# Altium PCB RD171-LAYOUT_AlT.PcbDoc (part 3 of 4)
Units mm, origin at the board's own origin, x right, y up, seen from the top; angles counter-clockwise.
Board outline 318.5 x 127 mm, 6 copper layers (TOP, Mid-Layer 1, Mid-Layer 2, Mid-Layer 3, Mid-Layer 4, BOTTOM), stack 1.422 mm thick; 473 components, 225 nets, 1188 pads, 1192 vias.
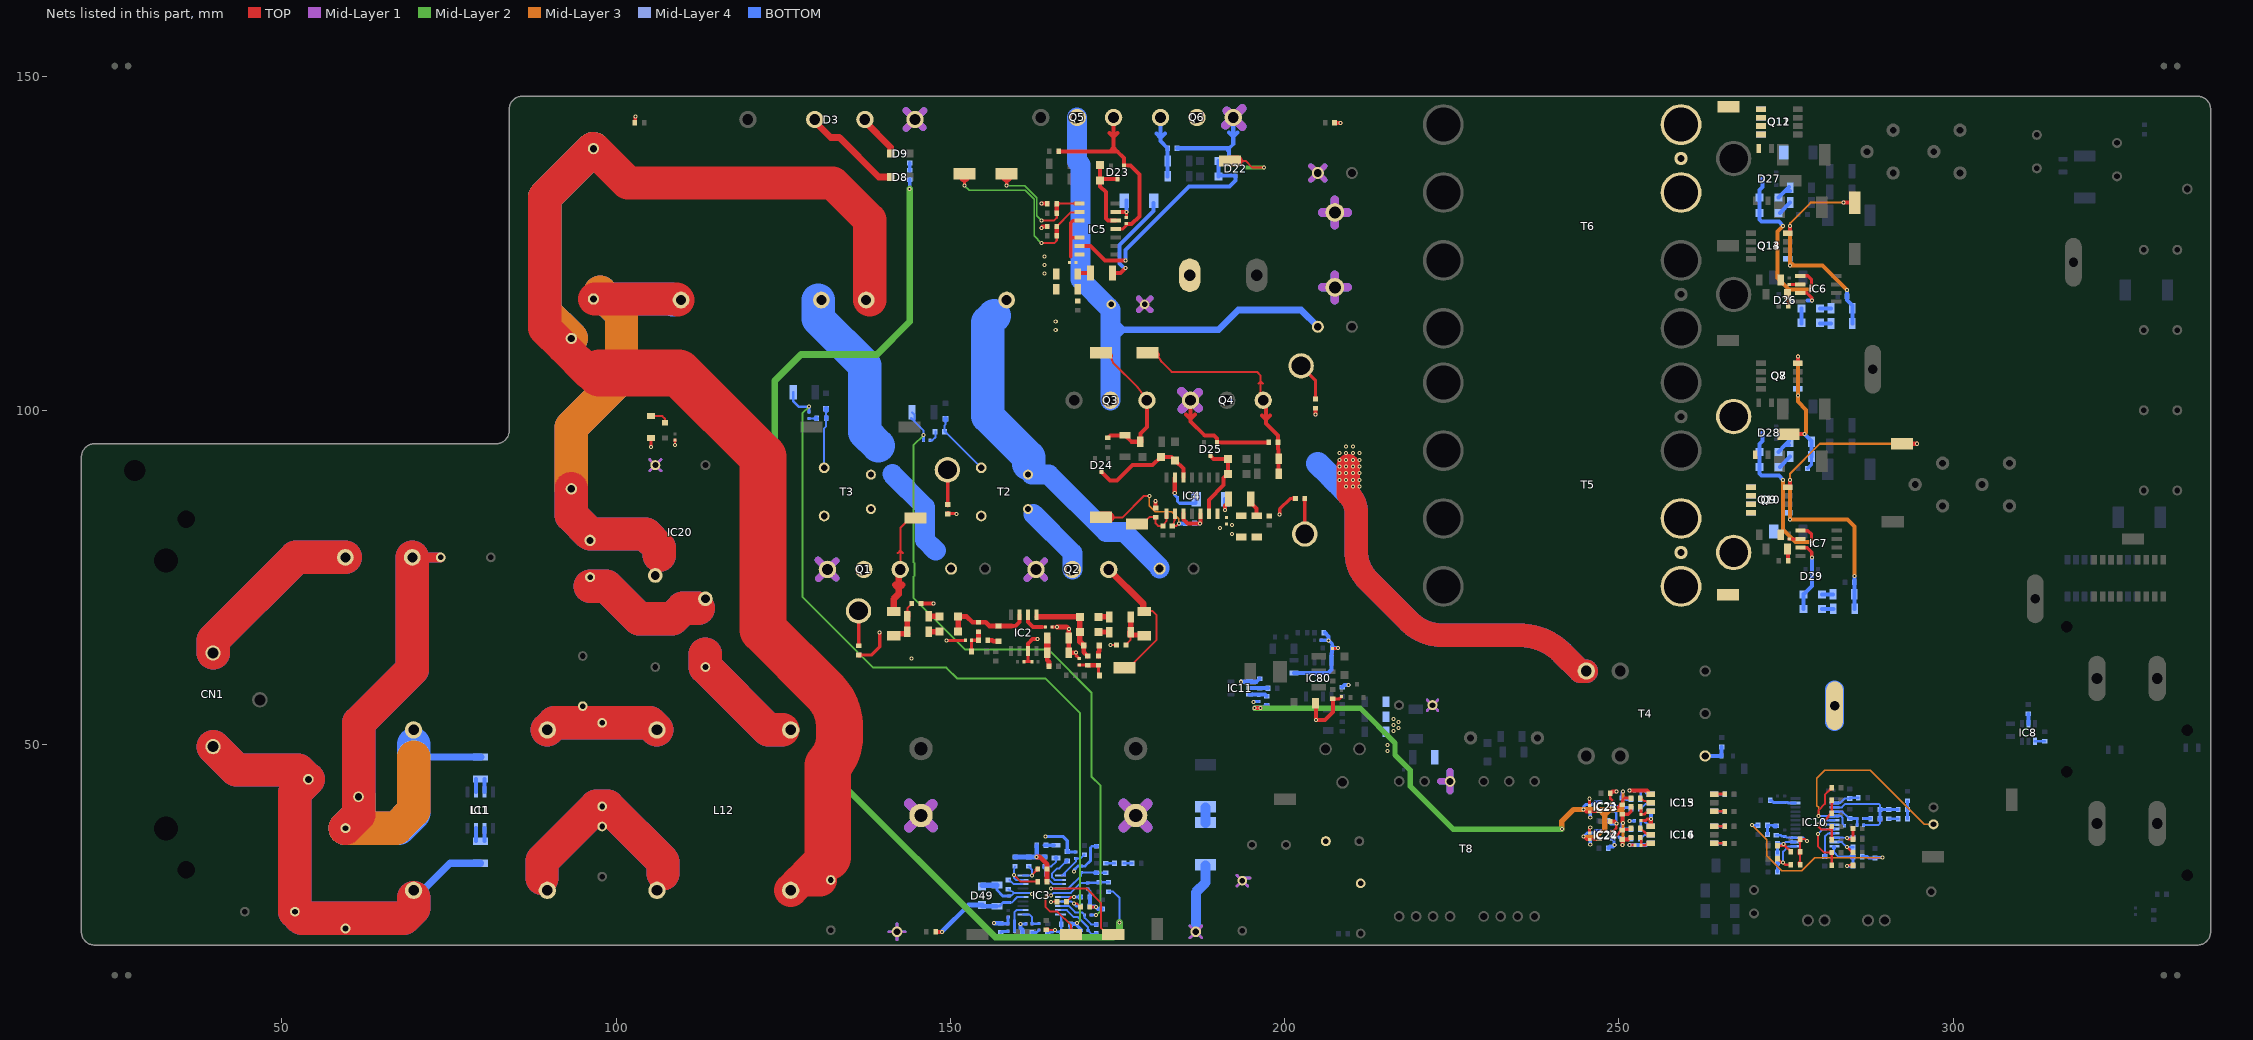
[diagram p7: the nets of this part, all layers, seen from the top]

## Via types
v1: diameter 0.6, hole 0.3, TOP to BOTTOM, 1184 vias
v2: diameter 7, hole 3.2, TOP to BOTTOM, 8 vias

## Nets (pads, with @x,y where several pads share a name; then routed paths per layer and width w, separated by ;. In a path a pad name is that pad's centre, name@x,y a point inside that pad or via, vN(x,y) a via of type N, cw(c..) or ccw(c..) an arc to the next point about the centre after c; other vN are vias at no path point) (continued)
PN: C1.1 C7.1 C34.1 C35.1 C36.1 C37.1 C38.1 C39.1 C40.1 C42.1 C43.1 C45.1 C47.1 C48.1 C49.1 C50.1 C53.1 C54.1 C55.1 C56.1 C57.1 C58.1 C62.1 C66.1 C67.1 C70.1 C71.1 C72.1 C73.1 C74.1 C75.1 C76.1 C77.1 C80.1 C81.1 C82.1 C83.1 C84.1 C85.1 C86.1 C87.1 C95.1 C96.1 C97.1 C98.1 C101.1 C103.1 C800.1 C802.1 C803.1 C804.1 C805.2 C806.2 C808.2 C811.2 C812.1 D3.4 D18.A D22.A D25.A D49.A D50.C HS5.1 HS6.1 IC2.3 IC3.16 IC4.3 IC4.5 IC5.3 IC5.5 IC11.1 IC13.4 IC14.4 IC15.4 IC16.4 IC20.2 IC21.3 IC22.3 IC23.3 IC24.3 IC80.GND Q1.S Q2.S Q4.S Q6.S R2.1 R7.1 R8.1 R29.1 R33.1 R71.1 R73.1 R90.1 R93.1 R96.1 R98.1 R99.1 R100.1 R101.1 R102.1 R103.1 R104.1 R174.1 R175.1 R176.1 R179.1 R187.1 R189.1 R191.1 R193.1 R198.1 R220.1 R221.1 R222.1 R223.1 R224.1 R225.1 R801.2 R807.1 R809.1 R811.2 R812.1 R813.1 R814.1 T2.2 T3.2 T8.4 TP43.1 TP45.1 | length 638.4
  TOP w0.3: v1(108.8,94.8) C70.1@108.8,95.396 ; v1(165.05,26.45) 165.459,26.5 R175.1@165.95,26.5 R175.1@166.01,26.5 ; v1(173.95,64.9) R71.1@174.85,64.9 R71.1@174.91,64.9
  TOP w0.4: v1(105.2,94.5) D50.C@105.2,95.695 ; C70.1@108.8,95.396 C70.1@108.8,95.525 C70.1@108.8,95.55 ; R191.1@248.7,42.7 248.7,41.95 248.95,41.7 IC23.3@248.95,41.25 ; IC24.3@248.95,37.05 249.15,37.05 249.6,37.5 v1(249.6,38.2)
  TOP w0.45: v1(149.4,65.6) C37.1@152.2,65.6 ; C81.1@161,62.4 161.585,62.4 ; IC2.3@161.585,63.95 161.585,62.4 ; C80.1@162.15,62.4 161.585,62.4 ; v1(168.75,63.75) 168.75,63.375 C35.1@169.25,62.875 ; C808.2@207.15,64.4 207.95,64.4 v1(208,64.45) ; R811.2@207.2,56.85 208.175,56.85 C805.2@208.5,57.175 ; C98.1@245.6,36.775 245.6,37.5 v1(245.7,37.6) ; C97.1@245.6,40.875 v1(245.6,41.9) ; v1(251.6,34.95) C74.1@252.35,34.95 ; C73.1@253.275,38.625 253.95,38.625 254.175,38.85 254.75,38.85 v1@254.8,38.85
  TOP w0.5: R225.1@102.86,143 v1(102.86,143.92) v1@102.87,143.93 ; R222.1@136.583,63.4 138.14,63.4 139.4,64.66 v1(139.4,66.8) ; R220.1@149.68,84.56 150.84,84.56 v1(150.9,84.5) ; C62.1@165.2,67.6 v1(165.95,67.6) ; 168,122.95 168,125.83 ; IC5.5@169.3,125.83 168,125.83 ; IC5.3@169.447,128.37 IC5.3@169.3,128.37 168.3,128.37 168,128.07 168,125.83 ; R176.1@170.85,25.7 v1(171.75,25.7) ; v1(199.25,84.4) 199.25,85.25 200.8,86.8 R221.1@201.325,86.8
  TOP w0.6: R73.1@145.65,71.1 v1(147.5,71.1) ; IC2.3@161.585,64 161.585,65.085 162.3,65.8 v1(163,65.8) ; v1(163.6,127.3) 163.8,127.5 C53.1@164.5,127.5 ; v1(163.6,130.9) C54.1@164.5,130.9 ; C57.1@180.7,85.4 v1(180.7,86.4) ; IC4.3@184.83,84.55 184.83,83.7 185.43,83.1 v1(187.35,83.1) 187.37,83.12 IC4.5@187.37,84.5 ; 185.25,99.35 185.9,98.7 ; Q4.S@185.9,101.5 185.9,98.7 ; 186.55,99.35 185.9,98.7 ; R33.1@197.6,95.2 D25.A@189.85,95.2 189.85,95.8 189.45,96.2 188.038,96.2 185.9,98.337 185.9,98.7 ; v1(204.6,99.35) R223.1@204.6,100.25 ; C806.2@204.65,56.2 v1(204.65,53.65) 206,53.65 207.2,54.85 R811.2@207.2,56.85 ; R224.1@207.45,143 v1(208.35,143) ; R193.1@248.7,38.5 249.3,38.5 v1(249.6,38.2) ; R191.1@248.7,42.7 249,43 v1(249.6,43) ; v1(251.55,43.1) 254.22,43.1 IC15.4@254.75,42.57 ; IC16.4@254.75,37.75 IC16.4@254.75,37.77 254.75,38.85 v1(254.8,38.9)
  TOP w0.7: D50.C@105.2,95.695 D50.C@105.2,95.863 ; R222.1@136.3,63.4 R222.1@136.583,63.4 ; v1(162.9,33.2) 163.35,33.2 164.45,32.1 R198.1@164.45,29.5 ; v1(165.95,67.6) 167.4,67.6 v1(167.7,67.3) C82.1@167.7,65.95 C83.1@167.7,63.75 ; C83.1@167.75,63.75 v1(168.75,63.75) ; R221.1@201.325,86.8 R221.1@201.6,86.8
  TOP w0.72: R220.1@149.6,84.56 R220.1@149.68,84.56
  Mid-Layer 1 w0.4: 105,90.95 IC20.2@105.85,91.8 ; 105,92.65 IC20.2@105.85,91.8 ; 106.7,90.95 IC20.2@105.85,91.8 ; 106.7,92.65 IC20.2@105.85,91.8 ; 140.8,22 TP43.1@142,22 ; 142,20.8 TP43.1@142,22 ; 142,23.2 TP43.1@142,22 ; 143.2,22 TP43.1@142,22 ; 185.8,21.1 TP45.1@186.7,22 ; 185.8,22.9 TP45.1@186.7,22 ; 187.6,21.1 TP45.1@186.7,22 ; 187.6,22.9 TP45.1@186.7,22 ; 192.85,28.85 C101.1@193.65,29.65 ; 192.85,30.45 C101.1@193.65,29.65 ; 194.45,28.85 C101.1@193.65,29.65 ; 194.85,30.05 194.05,30.05 C101.1@193.65,29.65 ; 221.3,55.1 C804.1@222.1,55.9 ; 221.3,56.7 C804.1@222.1,55.9 ; 222.9,55.1 C804.1@222.1,55.9 ; 222.9,56.7 C804.1@222.1,55.9
  Mid-Layer 1 w0.8: 178.15,114.95 C103.1@179.05,115.85 ; 178.15,116.75 C103.1@179.05,115.85 ; 179.95,114.95 C103.1@179.05,115.85 ; 179.95,116.75 C103.1@179.05,115.85 ; 203.9,134.45 D18.A@204.95,135.5 ; 203.9,136.55 D18.A@204.95,135.5 ; 206,134.45 D18.A@204.95,135.5 ; 206,136.55 D18.A@204.95,135.5
  Mid-Layer 1 w1: 130.2,77.6 Q1.S@131.6,76.2 ; 130.25,74.85 Q1.S@131.6,76.2 ; 132.9,74.9 Q1.S@131.6,76.2 ; 132.9,77.5 Q1.S@131.6,76.2 ; 143.35,144.85 D3.4@144.7,143.5 ; 143.4,142.2 D3.4@144.7,143.5 ; 145.95,142.25 D3.4@144.7,143.5 ; 146,144.8 D3.4@144.7,143.5 ; 161.4,77.6 Q2.S@162.8,76.2 ; 161.45,74.85 Q2.S@162.8,76.2 ; 164.1,74.9 Q2.S@162.8,76.2 ; 164.1,77.5 Q2.S@162.8,76.2 ; 223.3,44.5 T8.4@224.73,44.5 ; 224.73,43.1 T8.4@224.73,44.5 ; 224.73,46 T8.4@224.73,44.5
  Mid-Layer 1 w1.3: 184.55,102.85 Q4.S@185.9,101.5 ; 184.58,100.18 Q4.S@185.9,101.5 ; 187.09,100.31 Q4.S@185.9,101.5 ; 187.09,102.69 Q4.S@185.9,101.5 ; 191.14,142.64 Q6.S@192.3,143.8 ; 191.31,144.79 Q6.S@192.3,143.8 ; 193.65,142.45 Q6.S@192.3,143.8 ; 193.65,145.15 Q6.S@192.3,143.8 ; 205.6,118.4 HS5.1@207.5,118.4 ; 205.6,129.6 HS6.1@207.5,129.6 ; 207.5,116.5 HS5.1@207.5,118.4 ; 207.5,120.3 HS5.1@207.5,118.4 ; 207.5,127.7 HS6.1@207.5,129.6 ; 207.5,131.5 HS6.1@207.5,129.6 ; 209.4,118.4 HS5.1@207.5,118.4 ; 209.4,129.6 HS6.1@207.5,129.6
  Mid-Layer 1 w1.5: 143.8,37.6 C7.1@145.6,39.4 ; 143.8,41.2 C7.1@145.6,39.4 ; 147.35,37.65 C7.1@145.6,39.4 ; 147.35,41.15 C7.1@145.6,39.4 ; 175.9,37.6 C1.1@177.7,39.4 ; 175.9,41.2 C1.1@177.7,39.4 ; 179.5,37.6 C1.1@177.7,39.4 ; 179.5,41.2 C1.1@177.7,39.4
  Mid-Layer 2 w0.3: v1(128.85,100.55) 127.85,99.55 127.85,72.084 138.434,61.5 149.4,61.5 151.05,59.85 164.25,59.85 169.4,54.7 169.4,23.75 v1(168.95,23.3) ; v1(146,96.3) 144.45,94.75 144.45,77.3 144.63,77.12 144.63,75.28 144.45,75.1 144.45,71.951 152.151,64.25 164.6,64.25 171.1,57.75 171.1,45.2 172.45,43.85 172.45,25.15 v1(171.8,24.5)
  Mid-Layer 4 w0.4: 105,90.95 IC20.2@105.85,91.8 ; 105,92.65 IC20.2@105.85,91.8 ; 106.7,90.95 IC20.2@105.85,91.8 ; 106.7,92.65 IC20.2@105.85,91.8 ; 140.8,22 TP43.1@142,22 ; 142,20.8 TP43.1@142,22 ; 142,23.2 TP43.1@142,22 ; 143.2,22 TP43.1@142,22 ; 185.8,21.1 TP45.1@186.7,22 ; 185.8,22.9 TP45.1@186.7,22 ; 187.6,21.1 TP45.1@186.7,22 ; 187.6,22.9 TP45.1@186.7,22 ; 192.85,28.85 C101.1@193.65,29.65 ; 192.85,30.45 C101.1@193.65,29.65 ; 194.45,28.85 C101.1@193.65,29.65 ; 194.7,30.05 194.05,30.05 C101.1@193.65,29.65 ; 221.3,55.1 C804.1@222.1,55.9 ; 221.3,56.7 C804.1@222.1,55.9 ; 222.9,55.1 C804.1@222.1,55.9 ; 222.9,56.7 C804.1@222.1,55.9
  Mid-Layer 4 w0.8: 178.15,114.95 C103.1@179.05,115.85 ; 178.15,116.75 C103.1@179.05,115.85 ; 179.95,114.95 C103.1@179.05,115.85 ; 179.95,116.75 C103.1@179.05,115.85 ; 203.9,134.45 D18.A@204.95,135.5 ; 203.9,136.55 D18.A@204.95,135.5 ; 206,134.45 D18.A@204.95,135.5 ; 206,136.55 D18.A@204.95,135.5
  Mid-Layer 4 w1: 130.2,77.6 Q1.S@131.6,76.2 ; 130.25,74.85 Q1.S@131.6,76.2 ; 132.9,74.9 Q1.S@131.6,76.2 ; 132.9,77.5 Q1.S@131.6,76.2 ; 143.35,142.15 D3.4@144.7,143.5 ; 143.35,144.85 D3.4@144.7,143.5 ; 145.95,142.25 D3.4@144.7,143.5 ; 146.05,144.85 D3.4@144.7,143.5 ; 161.4,77.6 Q2.S@162.8,76.2 ; 161.45,74.85 Q2.S@162.8,76.2 ; 164.1,74.9 Q2.S@162.8,76.2 ; 164.1,77.5 Q2.S@162.8,76.2 ; 223.3,44.5 T8.4@224.73,44.5 ; 224.73,43 T8.4@224.73,44.5 ; 224.73,46 T8.4@224.73,44.5
  Mid-Layer 4 w1.3: 184.55,102.85 Q4.S@185.9,101.5 ; 184.58,100.18 Q4.S@185.9,101.5 ; 187.09,100.31 Q4.S@185.9,101.5 ; 187.09,102.69 Q4.S@185.9,101.5 ; 191.14,142.64 Q6.S@192.3,143.8 ; 191.31,144.79 Q6.S@192.3,143.8 ; 193.65,142.45 Q6.S@192.3,143.8 ; 193.65,145.15 Q6.S@192.3,143.8 ; 205.6,118.4 HS5.1@207.5,118.4 ; 205.6,129.6 HS6.1@207.5,129.6 ; 207.5,116.5 HS5.1@207.5,118.4 ; 207.5,120.3 HS5.1@207.5,118.4 ; 207.5,127.7 HS6.1@207.5,129.6 ; 207.5,131.5 HS6.1@207.5,129.6 ; 209.4,118.4 HS5.1@207.5,118.4 ; 209.4,129.6 HS6.1@207.5,129.6
  Mid-Layer 4 w1.5: 143.8,37.6 C7.1@145.6,39.4 ; 143.8,41.2 C7.1@145.6,39.4 ; 147.35,41.15 C7.1@145.6,39.4 ; 147.4,37.6 C7.1@145.6,39.4 ; 175.9,37.6 C1.1@177.7,39.4 ; 175.9,41.2 C1.1@177.7,39.4 ; 179.5,37.6 C1.1@177.7,39.4 ; 179.5,41.2 C1.1@177.7,39.4
  BOTTOM w0.3: R8.1@144.1,98.85 144.65,98.3 ; R8.1@144.25,99.7 144.65,99.3 144.65,98.3 ; v1(146,96.3) 146,96.95 144.65,98.3 ; C49.1@158.65,28.35 159.55,27.825 ; C47.1@158.8,27.325 158.85,27.4 159.125,27.4 159.55,27.825 ; v1(162.2,27.65) 161.85,27.825 IC3.16@160.85,27.825 159.55,27.825
  BOTTOM w0.4: R7.1@126.5,102.7 126.5,101.35 127.3,100.55 v1(128.85,100.55) C36.1@128.85,99.725 C36.1@128.85,99.7 ; C39.1@169.55,31.825 170.15,31.825 170.95,32.625 170.95,34.55 171.2,34.8 R90.1@171.725,34.8 ; IC22.3@249.05,35.85 249.25,35.85 249.25,35 v1(249.3,34.95) ; IC21.3@249.05,40.15 249.3,40.15 IC21.3@249.45,40 ; IC21.3@249.35,40.1 249.6,39.85 v1(249.6,38.2)
  BOTTOM w0.45: C34.1@145.975,95.5 145.975,96.275 v1(146,96.3) ; C48.1@156.95,29 156.95,28.95 156.95,28.25 157.875,27.325 C47.1@158.825,27.325 ; C43.1@158.625,23.2 C42.1@158.625,24.2 ; v1(160.5,23.2) C45.1@161.275,23.2 ; R104.1@167.692,33.925 C50.1@168.725,33.925 ; v1(168.45,31.05) 168.45,31.2 169.075,31.825 C39.1@169.55,31.825 ; v1@168.7,23.15 168.95,22.9 ; v1(168.95,23.3) 168.95,22.9 ; C76.1@169.625,22.225 168.95,22.9 ; C38.1@170.55,28.375 170.85,28.075 R102.1@170.85,27.2 ; C75.1@171.05,24.5 v1(171.8,24.5) ; v1(195.3,56.4) 195.325,56.425 C67.1@196.1,56.425 ; v1(245.7,35.05) C96.1@245.7,35.8 ; v1(245.7,39.1) C95.1@245.7,40.05 ; v1(251.55,38.6) C72.1@252.325,38.6 ; v1(251.55,43.1) C71.1@252.325,43.1
  BOTTOM w0.5: R98.1@157.6,23.2 C43.1@158.6,23.2 ; v1(164.25,36.25) 166.85,36.25 167.45,35.65 R104.1@167.45,34 ; C812.1@205.45,65.6 v1(206.55,65.6) 207.1,65.05 R807.1@207.1,64.45
  BOTTOM w0.55: R104.1@167.45,33.925 R104.1@167.692,33.925
  BOTTOM w0.6: v1(160.5,23.2) 160.5,22.6 160.75,22.35 R99.1@160.75,21.9 ; R96.1@167.95,21.8 C77.1@167.95,23.15 168.7,23.15 168.8,23.15 v1(168.95,23.3) ; R102.1@170.85,27.2 R101.1@170.85,25.8 171.65,25.8 v1(171.75,25.7) 172.05,25.4 R2.1@172.7,25.4 ; R29.1@183.9,139.2 191.2,139.2 ; C56.1@186.5,83.1 v1(187.35,83.1) ; 191.65,141.55 192.3,140.9 ; D22.A@191.7,137.1 191.7,138.7 ; Q6.S@192.3,143.8 192.3,140.9 ; 192.95,141.55 192.3,140.9 ; v1(193.45,59.4) IC11.1@194.7,59.4 195.8,59.4 C66.1@196.25,59.85 ; C802.1@201.4,60.7 206.45,60.7 207,61.25 ; R809.1@206,66.75 206.55,66.2 v1(206.55,65.6) ; 207.005,61.255 207.005,63.65 207.1,63.745 R807.1@207.1,64.45 ; R807.1@207.15,64.45 v1(208,64.45) ; C803.1@208.6,58.6 208.95,58.95 v1(209.55,58.95) ; R189.1@248.4,34.5 248.65,34.75 249.1,34.75 v1(249.3,34.95) ; R187.1@248.45,38.55 248.8,38.2 v1(249.6,38.2) ; v1(251.6,34.95) 254.05,34.95 254.33,35.23 IC14.4@254.75,35.23 ; v1(254.8,38.9) IC13.4@254.8,40.05 ; 191.2,139.2 191.7,139.2 ; 191.2,139.2 191.7,138.7 ; 191.7,138.7 191.7,139.2 ; 191.7,139.2 192.3,139.8 192.3,140.9
  BOTTOM w0.7: v1(156.55,23.3) R98.1@157.5,23.3 ; R100.1@159.65,33.2 R103.1@161.7,33.2 v1(162.9,33.2) ; R93.1@162.9,34.95 v1(162.9,33.2) ; C40.1@164.15,33.2 v1(162.9,33.2) ; R90.1@171.725,34.8 R90.1@171.85,34.8
  BOTTOM w0.8: D49.A@154.75,28.95 C48.1@156.95,28.95
  BOTTOM w1.5: TP45.1@186.7,22 186.7,27.9 188.15,29.35 R179.1@188.15,31.95
  other v1: 215.35,49.05 215.35,49.95 216.25,52 217.05,52.45 216.25,52.9 217.05,53.35 216.25,53.8 144.15,62.85 192.1,81.5 190.35,82.4 192.1,82.825 165.75,112.05 165.75,113.3 164.1,120.45 164.1,121.75 164.1,123
SIG1: C30.2 C78.2 F1.2 L11.2 R79.2 RV1.1 | length 179.1
  TOP w1.5: F1.2@69.5,78 C78.2@73.75,78
  TOP w5: C30.2@59.5,37.5 61.5,39.5 61.5,53.237 69.5,61.237 F1.2@69.5,78
  Mid-Layer 3 w5: RV1.1@61.5,42.25 61.5,39.5 C30.2@59.5,37.5 67.1,37.5 69.7,40.1 69.7,48.15
  Mid-Layer 4 w5: RV1.1@61.5,42.25 61.5,39.5 C30.2@59.5,37.5 67.1,37.5 69.7,40.1 69.7,48.15
  BOTTOM w1.1: 69.7,48.15 R79.2@79.75,48.15
  BOTTOM w1.5: F1.2@69.5,78 C78.2@73.75,78
  BOTTOM w5: F1.2@69.5,78 69.5,61.237 61.5,53.237 61.5,39.5 C30.2@59.5,37.5 67.5,37.5 69.7,39.7 69.7,48.15 69.7,50.05
SIG2: C30.1 C79.2 CN1.3 L11.3 R80.1 RV1.2 | length 124.8
  TOP w5: CN1.3@39.7,49.7 43.2,46.2 52.45,46.2 RV1.2@53.9,44.75 ; RV1.2@53.95,44.8 RV1.2@53.9,44.75 ; L11.3@69.75,27.1 69.75,25.55 68.2,24 52.95,24 C79.2@51.95,25 51.95,42.8 RV1.2@53.9,44.75
  BOTTOM w1.1: 71.1,28.2 75.15,32.25 R80.1@79.65,32.25
  BOTTOM w5: CN1.3@39.7,49.7 43.2,46.2 52.45,46.2 RV1.2@53.9,44.75 ; RV1.2@53.95,44.8 RV1.2@53.9,44.75 ; L11.3@69.75,27.1 69.75,25.55 68.2,24 52.95,24 C79.2@51.95,25 51.95,42.8 RV1.2@53.9,44.75
SIG6: C33.1 C63.2 C65.1 D3.3 D9.A L2.1 L12.4 | length 309.8
  TOP w1: D3.3@137.2,143.2 141.075,139.325 D9.A@141.075,138.4
  TOP w5: 97.55,105.6 96,105.6 92.075,109.525 89.3,112.3 89.3,131.85 C33.1@96.6,139.15 101.75,134 132.4,134 137.9,128.5 L2.1@137.9,116.5 ; 130.5,29.75 127.65,29.75 L12.4@126.1,28.2 130.5,32.6
  TOP w7: 97.55,105.6 109.35,105.6 121.95,93 121.95,67.2 131.262,57.888 cw(c126.1,52.726) 133.4,52.726 133.4,51.125 cw(c127.425,51.125) 131.65,46.9 131.65,33.2
  Mid-Layer 3 w5: C65.1@93.3,110.75 89.3,114.75 89.3,131.85 C33.1@96.6,139.15
  Mid-Layer 4 w5: C65.1@93.3,110.75 89.3,114.75 89.3,131.85 C33.1@96.6,139.15
  BOTTOM w5: C65.1@93.3,110.75 89.3,114.75 89.3,131.85 C33.1@96.6,139.15
SIG8: C33.2 C65.2 D3.2 D8.A IC20.3 L1.1 R138.2 | length 177.5
  TOP w1: D3.2@129.7,143.2 132.1,140.8 133.378,140.8 139.278,134.9 D8.A@141.075,134.9
  TOP w5: C65.2@93.3,88.25 93.3,84.3 96.1,81.5 104.4,81.5 106.45,79.45 106.45,78.3 ; C33.2@96.8,116.65 109.05,116.65 L1.1@109.2,116.5
  Mid-Layer 3 w5: C65.2@93.3,88.25 93.3,97.5 100.8,105 100.8,114.45 97.6,117.65
  Mid-Layer 4 w5: C65.2@93.3,88.25 93.3,97.5 100.8,105 100.8,114.45 97.6,117.65
  BOTTOM w5: 98.7,116.55 100.8,114.45 100.8,105 93.3,97.5 C65.2@93.3,88.25 93.3,84.3 96.1,81.5 104.4,81.5 106.45,79.45 106.45,78.3 ; 98.75,116.65 108.3,116.65 L1.1@108.45,116.5
SIG9: IC1.2 IC1.3 R79.1 | length 3.9
  BOTTOM w0.6: IC1.2@79.065,42.9 R79.1@79.065,44.85 ; IC1.3@80.335,42.9 R79.1@80.335,44.85
SIG10: IC1.6 IC1.7 R80.2 | length 3.9
  BOTTOM w0.6: R80.2@79.065,35.55 IC1.7@79.065,37.5 ; R80.2@80.335,35.55 IC1.6@80.335,37.5
SIG11: D2.A L2.2 T2.4 | length 50.3
  BOTTOM w3: T2.4@162.1,90.375 164.725,90.375 173.3,81.8 176.002,81.8 181.3,76.502 D2.A@181.3,76.31
  BOTTOM w5: 156.55,114.15 155.575,113.175 155.575,99.109 161.7,92.984 161.7,91.975
SIG12: D1.A L1.2 T3.4 | length 39.7
  BOTTOM w3: 141.3,90.45 146.2,85.55 146.2,80.6 147.8,79
  BOTTOM w5: L1.2@130.2,116.5 130.2,113.7 137.2,106.7 137.2,96.7 139.2,94.7
SIG15: D12.A R81.2 T2.1 | length 9.6
  BOTTOM w0.3: R81.2@149.1,96.8 149.1,97.7 149.25,97.85 D12.A@149.25,98.517 ; R81.2@149.327,96.722 149.611,96.389 T2.1@154.6,91.4
  BOTTOM w0.38: R81.2@149.26,96.8 R81.2@149.327,96.722
  BOTTOM w0.8: D12.A@149.25,98.517 D12.A@149.25,98.75
SIG16: C34.2 R81.1 | length 1.9
  BOTTOM w0.3: C34.2@146.925,95.5 147.3,95.5 147.76,95.96 R81.1@147.76,96.8
SIG18: Q2.D T2.3 | length 10.7
  BOTTOM w3: 162.45,84.452 168.25,78.652 Q2.D@168.25,76.2
SIG20: D13.A R85.2 T3.1 | length 9
  BOTTOM w0.3: T3.1@131.1,91.4 131.1,97.3 131.4,97.6 R85.2@131.4,98.725 ; R85.2@131.4,98.999 D13.A@131.4,100.036
  BOTTOM w0.7: R85.2@131.4,98.725 R85.2@131.4,98.8 R85.2@131.4,98.999
  BOTTOM w0.8: D13.A@131.4,100.036 D13.A@131.4,100.25
SIG21: C36.2 R85.1 | length 1.2
  BOTTOM w0.3: C36.2@129.016,98.775 R85.1@129.798,98.775
  BOTTOM w0.45: C36.2@128.85,98.775 C36.2@129.016,98.775
  BOTTOM w0.7: R85.1@129.798,98.775 R85.1@130,98.775
SIG22: Q1.D T3.3
SIG23: FB1.1 R71.2 R72.2 R108.2 | length 8.7
  TOP w0.3: 176.9,65.61 176.19,64.9 176.9,65.61 ; 176.9,65.61 176.9,66.41 176.9,65.61
  TOP w0.8: R108.2@176.95,66.4 FB1.1@179,66.4 ; R108.2@176.95,66.8 R72.2@176.95,69.1
  TOP w0.92: R108.2@176.9,66.41 176.9,66.8 R108.2@176.9,66.41
SIG24: C35.2 D31.A R82.2 R172.2 | length 4.5
  TOP w0.45: C35.2@169.25,61.925 R82.2@170.55,61.925
  TOP w0.5: R172.2@172.15,61.85 172.15,60.5 D31.A@172.3,60.35
  TOP w0.7: R82.2@170.55,61.85 R172.2@172.15,61.85
SIG25: C37.2 D33.A R86.2 R173.2 | length 4
  TOP w0.45: D33.A@153.175,63.9 C37.2@153.175,65.575
  TOP w0.5: C37.2@153.2,65.6 R173.2@154.2,65.6
  TOP w0.7: R173.2@154.2,65.6 R86.2@154.2,66.9
SIG27: FB2.1 R73.2 R74.2 R109.2 | length 8.9
  TOP w0.3: 143.55,70.39 143.55,69.7 143.55,70.39 ; 143.55,70.39 144.26,71.1 143.55,70.39
  TOP w0.8: FB2.1@141.5,66.3 141.8,66.6 R74.2@143.6,66.6 ; R74.2@143.55,66.9 R109.2@143.55,69.2
  TOP w0.92: R109.2@143.55,69.2 143.55,69.7 R109.2@143.55,69.2
SIG30: D32.C D38.A D39.C IC2.7 R86.1 | length 13.3
  TOP w0.6: 159.1,67.75 159.715,67.75 160.315,68.35 IC2.7@160.315,69.4
  TOP w0.7: D39.C@151.15,69.15 152.45,69.15 153.3,68.3 R86.1@154.2,68.3 155.25,68.3 155.8,67.75 D32.C@157.2,67.75
  TOP w0.8: D38.A@151.15,66.9 D39.C@151.15,69.15 ; D32.C@157.2,67.75 159.1,67.75
SIG39: R89.2 R91.1 | length 1.3
  BOTTOM w0.4: R89.2@173.25,32.25 R91.1@174.55,32.25
SIG40: R91.2 R92.1 | length 1.2
  BOTTOM w0.4: R91.2@175.95,32.25 R92.1@177.15,32.25
SIG43: C45.2 C46.2 IC3.11 | length 3.6
  BOTTOM w0.3: IC3.11@160.85,24.575 161.85,24.575 162.225,24.2 C45.2@162.225,23.363
  BOTTOM w0.4: C45.2@162.225,23.2 C46.2@163.25,23.2
  BOTTOM w0.45: C45.2@162.225,23.2 C45.2@162.225,23.363
SIG44: C46.1 R99.2 | length 1.3
  BOTTOM w0.4: R99.2@162.15,21.9 162.875,21.9 C46.1@163.25,22.275
SIG45: C43.2 C44.2 IC3.12 | length 4.1
  BOTTOM w0.3: 159.575,23.713 159.575,24.925 159.875,25.225 IC3.12@160.725,25.225
  BOTTOM w0.4: C44.2@159.575,22.1 C43.2@159.575,23.2 159.575,23.713
SIG46: C44.1 R98.2 | length 1.2
  BOTTOM w0.4: R98.2@157.5,21.9 157.65,22.05 158.575,22.05 C44.1@158.625,22.1
SIG47: C40.2 C41.2 IC3.3 | length 6.9
  BOTTOM w0.3: C40.2@164.15,31.6 164.15,30.35 165.375,29.125 IC3.3@166.575,29.125 ; C40.2@164.15,31.8 165.1,31.8 165.8,32.5 C41.2@165.8,33.025
  BOTTOM w0.7: C40.2@164.15,31.6 C40.2@164.15,31.8 ; C41.2@165.8,33.025 C41.2@165.8,33.05
SIG48: C41.1 R93.2 | length 1.5
  BOTTOM w0.5: R93.2@164.05,34.95 C41.1@165.55,34.95
SIG49: C39.2 IC3.4 R89.1 R227.2 TP8.1 | length 23
  TOP w0.3: v1(165.05,28.5) 170.35,28.5 172.55,26.3 172.55,22.55 TP8.1@173.5,21.6
  BOTTOM w0.3: v1(165.05,28.5) 165.45,28.475 IC3.4@166.55,28.475 ; IC3.4@166.575,28.475 167.625,28.475 169.55,30.4 C39.2@169.55,30.738 ; C39.2@169.717,30.85 R227.2@171.633,30.85
  BOTTOM w0.4: C39.2@169.55,30.85 C39.2@169.717,30.85 ; R227.2@171.85,30.85 R89.1@173.25,30.85
  BOTTOM w0.45: C39.2@169.55,30.738 C39.2@169.55,30.875
  BOTTOM w0.7: R227.2@171.633,30.85 R227.2@171.85,30.85
SIG50: C49.2 IC3.18 | length 2.3
  BOTTOM w0.3: C49.2@158.8,29.775 159.45,29.125 IC3.18@160.8,29.125
SIG51: C50.2 IC3.1 R171.1 | length 6.9
  BOTTOM w0.3: IC3.1@166.7,30.45 167.1,30.85 ; IC3.1@167.1,30.425 167.1,30.85 ; C50.2@168.75,32.838 168.75,32.5 167.1,30.85 ; 169.465,32.975 170.05,33.56 169.465,32.975 ; 169.465,32.975 168.838,32.975 169.465,32.975
  BOTTOM w0.45: C50.2@168.75,32.838 C50.2@168.75,32.975 ; C50.2@168.75,32.975 168.838,32.975 C50.2@168.75,32.975
SIG52: IC3.19 R100.2 R198.2 | length 7.2
  TOP w0.3: v1(159.5,30.5) 160.5,29.5 R198.2@162.913,29.5
  TOP w0.58: R198.2@162.913,29.5 R198.2@163.11,29.5
  BOTTOM w0.3: R100.2@159.65,31.8 159.5,31.2 v1(159.5,30.5) 159.5,30.075 159.8,29.775 IC3.19@160.85,29.775
SIG53: IC3.7 R101.2 R176.2 | length 4.3
  TOP w0.3: v1(168.45,26.2) 168.95,26.2 R176.2@169.45,25.7
  BOTTOM w0.3: IC3.7@166.575,26.525 168.125,26.525 v1(168.45,26.2)
  BOTTOM w0.4: v1(168.45,26.2) 168.85,25.8 R101.2@169.3,25.8
  BOTTOM w0.6: R101.2@169.3,25.8 R101.2@169.4,25.8
SIG54: IC3.6 R102.2 R175.2 | length 4.3
  TOP w0.3: R175.2@167.35,26.5 168.05,27.2 v1(168.45,27.2)
  BOTTOM w0.3: IC3.6@166.575,27.175 168.038,27.175 v1(168.45,27.2)
  BOTTOM w0.4: v1(168.45,27.2) R102.2@169.425,27.2
  BOTTOM w0.7: R102.2@169.425,27.2 R102.2@169.45,27.2
SIG55: IC3.20 R103.2 R174.2 | length 4.2
  TOP w0.3: v1(162.2,30.425) R174.2@162.931,31.264
  TOP w0.7: R174.2@162.931,31.264 R174.2@163.05,31.4
  BOTTOM w0.3: IC3.20@160.85,30.425 v1(162.2,30.425) 162.2,31.3 R103.2@161.7,31.8
SIG56: IC3.2 R104.2 | length 5.2
  BOTTOM w0.3: IC3.2@166.575,29.775 165.575,29.775 165.2,30.15 165.2,30.75 165.95,31.5 166.29,31.5 R104.2@167.255,32.465
  BOTTOM w0.58: R104.2@167.255,32.465 R104.2@167.45,32.66
SIG60: R94.2 R95.1 | length 1.2
  BOTTOM w0.5: R94.2@143.9,135.84 R95.1@143.9,137.06
SIG61: R1.2 R94.1 | length 168
  Mid-Layer 2 w1: v1(143.9,133.1) 143.9,113.25 139,108.35 127.65,108.35 123.7,104.4 123.7,69.2 133,59.9 133,44.9 156.7,21.2 174.35,21.2 175.3,22.15 v1(175.3,23.4)
  BOTTOM w0.3: R1.2@173.65,28 174.35,28 175.3,27.05 v1(175.3,23.4)
  BOTTOM w0.5: v1(143.9,133.1) R94.1@143.9,134.56
SIG62: C38.2 IC3.5 R1.1 R228.2 TP7.1 | length 18
  TOP w0.3: v1(165.05,27.45) 164.5,27.45 164.25,27.2 164.25,25.7 164.95,25 166,25 168.05,22.95 TP7.1@168.05,21.675
  TOP w1.7: TP7.1@168.05,21.6 TP7.1@168.05,21.675
  BOTTOM w0.3: v1(165.05,27.45) 165.425,27.825 IC3.5@166.55,27.825 ; IC3.5@166.575,27.825 167.995,27.825 169.495,29.325 C38.2@170.375,29.325
  BOTTOM w0.4: C38.2@170.55,29.325 R228.2@172.25,29.325 ; R228.2@172.25,29.4 R1.1@173.65,29.4
  BOTTOM w0.45: C38.2@170.375,29.325 C38.2@170.55,29.325
SIG65: C19.2 D17.C IC4.13 | length 7.1
  TOP w0.6: v1(183.55,87.65) IC4.13@183.55,89.9
  BOTTOM w0.45: v1(183.55,87.65) 183.55,87.35 C19.2@183.975,86.925 ; C19.2@183.975,86.9 183.975,86.375 184.25,86.1 186.75,86.1 D17.C@186.75,86.6
SIG75: C18.2 D16.C IC5.13 | length 4.1
  TOP w0.45: C18.2@176.3,128.875 v1(176.3,129.65)
  TOP w0.6: IC5.13@174.7,129.64 v1@176.3,129.64
  BOTTOM w0.6: v1(176.3,129.65) D16.C@176.3,131.35
SIG82: Q6.G R29.2 R136.2 R137.2 | length 11
  BOTTOM w0.6: 180.8,141.4 181.45,140.75 ; Q6.G@181.45,143.77 181.45,140.75 ; 182.1,141.4 181.45,140.75 ; R136.2@182.5,135 R137.2@182.5,137.3 R29.2@182.5,139.2 181.45,140.25 181.45,140.75
SIG86: C47.2 C48.2 D49.C IC3.15 R120.2 | length 14.8
  TOP w0.6: R120.2@147.85,22 v1(148.7,22)
  BOTTOM w0.3: C47.2@158.8,26.375 159.15,26.375 159.95,27.175 IC3.15@160.85,27.175
  BOTTOM w0.45: C48.2@157.325,25.825 157.875,26.375 C47.2@158.8,26.375
  BOTTOM w0.7: v1(148.7,22) 152.7,26 D49.C@154.75,26 D49.C@154.8,26 ; D49.C@154.775,25.8 C48.2@156.925,25.8
SIG89: C54.2 IC5.1 R111.2 TP38.1 | length 18.7
  TOP w0.3: v1(163.6,128.4) 165.5,128.4 165.9,128.8 R111.2@165.9,129.5 ; C54.2@166.117,130.91 IC5.1@168.625,130.91
  TOP w0.5: v1(158.4,133.6) TP38.1@158.4,134.95
  TOP w0.6: R111.2@165.9,129.5 C54.2@165.9,130.9 ; IC5.1@168.625,130.91 IC5.1@169.3,130.91
  TOP w0.7: C54.2@165.9,130.91 C54.2@166.117,130.91
  TOP w1.7: TP38.1@158.4,134.95 TP38.1@158.4,135.4
  Mid-Layer 2 w0.2: v1(158.4,133.6) 161.1,133.6 162.9,131.8 162.9,129.1 v1(163.6,128.4)
SIG90: C53.2 IC5.2 R110.2 TP39.1 | length 28.9
  TOP w0.3: v1(163.6,125) 165.5,125 165.9,125.4 R110.2@165.9,126.1 ; C53.2@165.9,127.5 168,129.6 IC5.2@168.782,129.6
  TOP w0.5: v1(152.1,133.6) TP39.1@152.1,134.95
  TOP w0.52: IC5.2@168.782,129.6 IC5.2@169.3,129.6
  TOP w0.6: R110.2@165.9,126.1 C53.2@165.9,127.5
  TOP w1.7: TP39.1@152.1,134.95 TP39.1@152.1,135.4
  Mid-Layer 2 w0.2: v1(152.1,133.6) 152.8,132.9 161.2,132.9 162.5,131.6 162.5,126.1 v1(163.6,125)
SIG91: C58.2 C84.2 C85.2 IC4.7 R115.1 R122.2 | length 2.3
  TOP w0.6: R115.1@194.9,86.2 195.8,85.3 C85.2@195.8,84.25
SIG92: D17.A R115.2 | length 3
  TOP w0.6: v1(191.1,85.1) 191.1,85.75 R115.2@191.6,86.25
  BOTTOM w0.6: v1(191.1,85.1) D17.A@191.1,86.7
SIG93: C57.2 IC4.1 R113.2 TP9.1 | length 6.6
  TOP w0.3: TP9.1@178.7,83 179.615,83.887 179.683,83.953 179.79,84.06 C57.2@180.68,84.06 ; C57.2@180.7,83.85 180.7,83.1 181.1,82.7 R113.2@181.8,82.7 182.29,83.45 IC4.1@182.29,84.075
  TOP w0.58: C57.2@180.68,84.06 C57.2@180.7,84.06
  TOP w0.6: C57.2@180.7,83.85 C57.2@180.7,84.05 ; IC4.1@182.29,84.075 IC4.1@182.29,84.55
SIG94: C56.2 IC4.2 R112.2 TP10.1 | length 19.9
  TOP w0.3: TP10.1@173.683,84 175.75,84 178.95,87.2 v1(179.75,87.2) ; IC4.2@183.55,84.065 183.55,83.6 R112.2@183.2,82.7 183.75,82.7 v1(184.15,83.1)
  TOP w0.58: IC4.2@183.55,84.065 IC4.2@183.55,84.55
  TOP w1.7: TP10.1@172.5,84 TP10.1@173.683,84
  Mid-Layer 3 w0.2: v1(179.75,87.2) 179.75,85.7 180.625,84.825 183.075,84.825 184.15,83.75 v1(184.15,83.1)
  BOTTOM w0.6: v1(184.15,83.1) C56.2@185.1,83.1
SIG95: D16.A R114.2 | length 14.6
  TOP w0.6: R114.2@174.25,120.55 175.45,120.55 v1(176.2,121.3)
  BOTTOM w0.6: v1(176.2,121.3) 175.95,121.3 175.3,121.95 175.3,124.7 180.4,129.8 D16.A@180.4,131
SIG100: D36.C R72.1 | length 1.6
  TOP w0.8: D36.C@172.15,69.1 R72.1@173.75,69.1
SIG101: D37.A R108.1 | length 1.6
  TOP w0.8: D37.A@172.15,66.85 R108.1@173.75,66.85
SIG102: D30.C D36.A D37.C IC2.5 R82.1 | length 12.7
  TOP w0.7: D30.C@169.95,64.8 169.95,63.8 R82.1@170.5,63.25
  TOP w0.8: IC2.5@162.95,69.1 D36.A@169.35,69.1 D37.C@169.35,66.85 169.35,65.4 D30.C@169.95,64.8
SIG104: C62.2 C82.2 C83.2 IC2.6 R121.2 | length 8.3
  TOP w0.5: 163.7,67.6 C62.2@164.2,67.6
  TOP w0.6: IC2.6@161.585,69.4 161.585,68.35 162.335,67.6 163.7,67.6
  TOP w0.7: C83.2@164.5,63.65 164.5,62.65 164.75,62.4 R121.2@164.75,61.7
  TOP w1: C83.2@164.5,63.7 C82.2@164.5,65.95
SIG105: D39.A R109.1 | length 1.6
  TOP w0.8: R109.1@146.75,69.2 D39.A@148.35,69.2
SIG106: D38.C R74.1 | length 1.6
  TOP w0.8: R74.1@146.75,66.9 D38.C@148.35,66.9
SIG115: C106.2 D34.A Q9.5 Q9.6 Q9.7 Q9.8 Q10.5 Q10.6 Q10.7 Q10.8 T5.14
SIG116: D29.C D57.A D58.C IC7.7 | length 11
  TOP w0.5: IC7.7@277.15,79.465 278.16,79.465 278.85,78.775 v1(278.85,78)
  BOTTOM w0.6: D57.A@277.6,70.3 D58.C@277.6,72.5 ; D58.C@277.6,72.45 278.85,73.7 278.85,74.25 v1(278.85,78)
SIG117: D28.C D55.A D56.C IC7.5 | length 26
  TOP w0.5: IC7.5@277.15,82.005 278.245,82.005 278.8,81.45 v1(278.8,80.05)
  Mid-Layer 3 w0.6: v1(274.55,89.6) 274.55,82.15 276.4,80.3 278.55,80.3 v1(278.8,80.05)
  BOTTOM w0.6: D28.C@271.5,96.6 271.5,95.4 271.05,94.95 D56.C@271.05,93.8 271.05,91.5 271.05,90.55 271.35,90.25 273.9,90.25 v1(274.55,89.6)
SIG118: Q9.4 Q10.4 R24.2 R25.2 R215.2 TP20.1 | length 54.4
  TOP w0.6: Q9.4@275.6,88.5 v1(275.6,89.6) ; TP20.1@292.35,95 v1(294.55,95)
  Mid-Layer 3 w0.3: v1(275.6,89.6) 275.6,90.55 280.05,95 v1(294.55,95)
  Mid-Layer 3 w0.6: v1(275.6,89.6) v1(275.6,83.65) 284.15,83.65 285.2,82.6 v1(285.2,75.25)
  BOTTOM w0.6: v1(275.6,83.65) Q10.4@275.6,84.7 ; R24.2@285.2,70.3 R215.2@285.2,72.5 R25.2@285.2,74.3 v1(285.2,75.25)
SIG121: C60.2 C90.2 C91.2 IC7.6 R124.2 | length 3.4
  TOP w0.45: C60.2@275.425,80.725 IC7.6@277.1,80.725
  TOP w0.6: R124.2@275.3,77.5 C90.2@275.3,79.25
SIG122: C59.1 IC8.1 | length 1.5
  BOTTOM w0.4: IC8.1@312.2,50.5 C59.1@313.7,50.5
SIG124: C61.2 C88.2 C89.2 IC6.6 R125.2 | length 3.4
  TOP w0.45: C61.2@275.425,118.825 IC6.6@277.1,118.825
  TOP w0.6: R125.2@275.3,115.6 C89.2@275.3,117.35
SIG126: D26.C D53.A D54.C IC6.7 | length 5.3
  TOP w0.5: IC6.7@277.1,117.565 278.11,117.565 278.85,116.825 v1(278.85,116.45)
  BOTTOM w0.6: D53.A@277.3,113 D53.A@277.3,113.1 D54.C@277.3,115.25 ; 278.2,116.45 v1(278.85,116.45)
SIG127: D27.C D51.A D52.C IC6.5 | length 27.5
  TOP w0.5: IC6.5@277.1,120.105 278.245,120.105 278.8,119.55 v1(278.8,118.1)
  Mid-Layer 3 w0.6: v1(274.55,127.6) 273.7,126.75 273.7,119.8 275.4,118.1 v1(278.8,118.1)
  BOTTOM w0.6: D27.C@271.5,134.6 271.5,133.4 271.05,132.95 D52.C@271.05,131.8 271.05,129.5 271.05,128.55 271.35,128.25 273.9,128.25 v1(274.55,127.6)
SIG128: Q13.4 Q14.4 R20.2 R21.2 R213.2 TP19.1 | length 36.1
  TOP w0.6: Q13.4@275.6,126.5 v1(275.6,127.6) ; v1(283.55,131.05) TP19.1@285.25,131.05
  Mid-Layer 3 w0.3: v1(275.6,127.6) 275.6,128 278.65,131.05 v1(283.55,131.05)
  Mid-Layer 3 w0.6: 275.6,122.2 276.15,121.65 v1(275.6,121.65) ; v1(275.6,127.6) v1(275.6,121.65) ; v1(284.1,118) 280.45,121.65 v1(275.6,121.65)
  BOTTOM w0.6: v1(275.6,121.65) Q14.4@275.6,122.7 ; v1(284.1,118) R21.2@284.1,117.05 284.1,116.5 284.9,115.7 284.9,115.3 R20.2@284.9,113
SIG135: C105.2 D21.A Q11.5 Q11.6 Q11.7 Q11.8 Q12.5 Q12.6 Q12.7 Q12.8 T6.10 T6.11 T6.12 TP30.1
SIG136: IC8.5 R6.1 | length 1.5
  BOTTOM w0.6: IC8.5@311.25,53.1 R6.1@311.25,54.6
SIG148: IC10.6 R51.2 R180.2 | length 8.5
  TOP w0.3: v1(279.8,38.05) 279.8,37.75 280.25,37.3 281.3,37.3 ; 281.8,37.3 281.3,37.3 ; R180.2@281.8,37.75 281.35,37.3 281.3,37.3
  TOP w0.4: R51.2@281.8,35.75 R180.2@281.8,37.75
  BOTTOM w0.3: v1(279.8,38.05) 280.079,38.354 280.5,38.775 281.025,38.775 281.125,38.675 IC10.6@281.65,38.675
  BOTTOM w0.4: IC10.6@281.5,38.675 282.162,38.675 IC10.6@281.65,38.675
SIG149: IC10.7 R52.2 R181.2 | length 5.4
  TOP w0.4: v1(280.8,38.05) 280.8,38.75 R52.2@281.8,39.75 R181.2@281.8,41.65
  BOTTOM w0.3: v1(280.8,38.05) 281.2,38.05 281.225,38.025 IC10.7@281.525,38.025
  BOTTOM w0.4: IC10.7@281.525,38.025 IC10.7@282.2,38.025
SIG150: IC10.8 R53.2 R182.2 | length 9
  TOP w0.3: v1(279.8,36.65) 279.8,34.75 280.7,33.85 R53.2@281.663,33.85
  TOP w0.4: R182.2@281.8,31.95 R53.2@281.8,33.9
  TOP w0.58: R53.2@281.663,33.85 R53.2@281.86,33.85
  BOTTOM w0.3: v1(279.8,36.65) 280.425,37.275 281,37.275 281.1,37.375 IC10.8@281.65,37.375
  BOTTOM w0.4: IC10.8@281.65,37.375 IC10.8@282.2,37.375
SIG151: IC10.9 R54.2 | length 5.2
  BOTTOM w0.3: R54.2@280.8,33.387 280.8,36.25 281.275,36.725 IC10.9@281.65,36.725
  BOTTOM w0.4: IC10.9@281.57,36.725 282.162,36.725 IC10.9@281.65,36.725
  BOTTOM w0.58: R54.2@280.8,33.19 R54.2@280.8,33.387
SIG152: C25.2 CN10.1 IC10.5 R50.2 | length 36.8
  TOP w0.3: v1(279.85,39.35) 279.85,40.2 280.8,41.15 280.8,42.49 R50.2@281.665,43.355
  TOP w0.58: R50.2@281.665,43.355 R50.2@281.86,43.55
  Mid-Layer 3 w0.2: v1(279.85,39.35) 279.85,40.6 279.6,40.85 279.6,45 280.75,46.15 287.6,46.15 295.67,38.08 CN10.1@297.05,38.08
  BOTTOM w0.3: v1@279.8,39.35 280.212,39.325 IC10.5@281.483,39.325 ; IC10.5@282.75,39.325 283.18,39.325 283.405,39.1 283.405,38.22 C25.2@283.775,37.85
  BOTTOM w0.4: IC10.5@281.483,39.325 IC10.5@282.2,39.325 ; IC10.5@282.55,39.325 IC10.5@282.75,39.325
SIG154: IC10.2 R44.1 R45.2 | length 4
  BOTTOM w0.3: IC10.2@282.825,41.275 283.125,41.275 283.8,41.95 R44.1@284.5,41.95
  BOTTOM w0.4: IC10.2@282.162,41.275 IC10.2@282.825,41.275 ; R44.1@284.5,41.95 284.6,42.05 R45.2@285.8,42.05
SIG156: C20.1 C22.1 IC10.3 R42.1 R43.2 R47.2 | length 15.8
  BOTTOM w0.3: IC10.3@282.777,40.625 283.324,40.625 283.849,41.15 288.85,41.15 289.05,40.95 R43.2@289.05,40.3 ; C22.1@286.75,37.95 288.75,37.95 289.05,38.25 R47.2@289.05,38.775
  BOTTOM w0.4: R47.2@289.05,38.9 R43.2@289.05,40.3 C20.1@290.35,40.3 R42.1@291.75,40.3 ; IC10.3@282.162,40.625 282.777,40.625 IC10.3@282.162,40.625
  BOTTOM w0.45: C22.1@286.575,37.95 C22.1@286.75,37.95
  BOTTOM w0.7: R47.2@289.05,38.775 R47.2@289.05,38.9
SIG157: R42.2 R46.2 R75.1 | length 2.6
  BOTTOM w0.4: R46.2@293.15,38.9 R42.2@293.15,40.3 R75.1@293.15,41.55
SIG167: C21.1 R47.1 | length 1
  BOTTOM w0.4: C21.1@286.6,38.95 R47.1@287.65,38.95
SIG168: C21.2 C22.2 IC10.4 R48.2 | length 4.7
  BOTTOM w0.3: IC10.4@282.895,39.975 283.425,39.975 R48.2@284.45,38.95
  BOTTOM w0.4: IC10.4@282.3,39.975 IC10.4@282.895,39.975 ; R48.2@284.5,38.95 C21.2@285.625,38.95 C22.2@285.625,37.95
SIG170: C20.2 R46.1 | length 1.4
  BOTTOM w0.4: C20.2@290.35,38.9 R46.1@291.75,38.9
SIG171: IC10.14 R65.1 R66.2 R209.2 R211.1 | length 7.8
  TOP w0.4: R209.2@273.7,34.85 274.3,34.85 ; R65.1@275.7,34 274.85,34.85 ; 274.3,34.85 v1(274.6,35.15) ; 274.3,34.85 274.85,34.85 ; 274.3,34.85 v1(274.6,35.15) ; v1(274.6,35.15) 274.85,34.9 274.85,34.85
  BOTTOM w0.3: v1(274.6,35.15) 274.875,35.425 IC10.14@275.683,35.425
  BOTTOM w0.4: R211.1@273.7,33.75 R66.2@273.7,35.15 v1(274.6,35.15) ; IC10.14@275.683,35.425 IC10.14@276.4,35.425
SIG172: IC10.13 R63.1 R64.2 R208.2 R210.1 | length 8.8
  TOP w0.3: 274.24,32.35 v1(274.55,32.35)
  TOP w0.4: R208.2@273.7,32.95 274.3,32.35 v1(274.55,32.35) 274.85,32.05 R63.1@275.7,32.05
  BOTTOM w0.3: v1(274.55,32.35) 274.55,34 275.325,34.775 IC10.13@275.85,34.775
  BOTTOM w0.4: R210.1@273.7,30.95 R64.2@273.7,32.35 v1(274.55,32.35) ; IC10.13@275.85,34.775 IC10.13@276.4,34.775
SIG173: C26.2 IC10.15 R63.2 R65.2 R69.1 R70.2 | length 14.3
  TOP w0.3: 277.8,35.85 v1(278.1,35.55) 277.8,35.85 ; 277.8,35.85 277.04,35.85 277.8,35.85 ; R63.2@277.04,32.27 277.04,33.73 R63.2@277.04,32.27 ; R65.2@277.04,34.17 277.04,35.63 R65.2@277.04,34.17
  TOP w0.72: R65.2@277.04,33.95 277.04,34.17 R65.2@277.04,33.95 ; R65.2@277.04,33.95 277.04,33.73 R65.2@277.04,33.95 ; R63.2@277.04,32.05 277.04,32.27 R63.2@277.04,32.05 ; R70.2@277.04,35.63 277.04,35.85 R70.2@277.04,35.63
  BOTTOM w0.3: C26.2@274.8,36.275 275.102,36.124 275.2,36.075 IC10.15@275.825,36.075 ; IC10.15@277.03,36.075 277.575,36.075 v1(278.1,35.55)
  BOTTOM w0.4: R69.1@273.5,36.45 274.175,36.45 274.35,36.275 C26.2@274.8,36.275 ; IC10.15@275.825,36.075 IC10.15@276.4,36.075
SIG174: R59.2 R67.1 R69.2 | length 2.9
  BOTTOM w0.4: R67.1@272.2,36.55 R59.2@272.2,37.95 R69.2@273.5,37.95
  BOTTOM w0.72: R69.2@273.28,37.79 R69.2@273.5,37.79
SIG175: R59.1 R60.2 R62.1 | length 28.5
  Mid-Layer 3 w0.2: v1(269.9,37.95) 272.1,35.75 272.1,33.4 274.35,31.15 277.3,31.15 279.25,33.1 v1(289.4,33.1)
  BOTTOM w0.4: v1(269.9,37.95) R59.1@270.8,37.95 ; R60.2@286.4,33.25 287.15,33.25 287.35,33.05 R62.1@288.3,33.05 ; R62.1@288.3,33.1 v1(289.4,33.1)
SIG177: IC10.12 R60.1 R61.2 R184.2 | length 7.6
  TOP w0.4: v1(284.1,31.85) 284.2,31.95 R184.2@285,31.95
  BOTTOM w0.3: 282.162,34.562 282.162,33.888 282.8,33.25 R60.1@284.783,33.25 ; v1(284.1,31.85) 284.52,31.85
  BOTTOM w0.4: v1(284.1,31.85) R61.2@285,31.85 R60.1@285,33.25
  BOTTOM w0.6: 282.162,34.562 IC10.12@282.162,34.675
  BOTTOM w0.7: R60.1@284.783,33.25 R60.1@285,33.25
SIG179: IC10.10 R55.2 R57.1 R207.1 | length 6.1
  TOP w0.4: v1(284.1,36.05) 284.3,35.85 R55.2@285,35.85 R207.1@285,37.45
  BOTTOM w0.3: IC10.10@282.815,36.075 283.475,36.075 v1(284.1,36.05)
  BOTTOM w0.4: v1(284.1,36.05) R57.1@285,36.05 ; IC10.10@282.162,36.075 282.815,36.075 IC10.10@282.162,36.075
SIG181: IC10.11 R56.2 R58.1 | length 3.7
  TOP w0.4: v1(284.1,34.65) R58.1@284.9,33.85
  BOTTOM w0.3: IC10.11@282.755,35.425 283.325,35.425 v1(284.1,34.65)
  BOTTOM w0.4: v1(284.1,34.65) R56.2@285,34.65
SIG183: C23.2 C24.2 IC10.23 R49.2 | length 4
  BOTTOM w0.4: C24.2@274.8,41.375 275.2,41.375 275.3,41.275 IC10.23@276.4,41.275
  BOTTOM w0.45: R49.2@272.6,41.65 272.8,41.65 273.075,41.375 C23.2@273.7,41.375 C24.2@274.8,41.375
SIG185: C67.2 IC11.3 R117.1 | length 2.8
  BOTTOM w0.4: C67.2@196.1,57.375 C67.2@196.1,57.5
  BOTTOM w0.6: IC11.3@194.7,57.5 196.1,57.5 197.05,57.5 R117.1@197.3,57.25
SIG193: CN1.1 F1.1 | length 53.7
  TOP w5: CN1.1@39.7,63.7 39.7,65.6 52.1,78 F1.1@59.5,78
  BOTTOM w5: CN1.1@39.7,63.7 39.7,65.6 52.1,78 F1.1@59.5,78
SIG199: C32.2 C52.2 L11.1 L12.2 | length 34.5
  TOP w5: L11.1@89.7,52.2 90.75,53.25 C52.2@97.9,53.25 105.05,53.25 L12.2@106.1,52.2
  BOTTOM w5: L11.1@89.7,52.2 90.75,53.25 C52.2@97.9,53.25 105.05,53.25 L12.2@106.1,52.2
SIG200: C31.2 C52.1 L11.4 L12.3 | length 58
  TOP w5: 88.9,30 88.9,32.6 97.05,40.75 C52.1@97.8,40.75 ; C52.1@98.1,40.75 98.75,40.75 107,32.5 107,30.7
  BOTTOM w5: 88.9,30 88.9,32.6 97.05,40.75 C52.1@97.8,40.75 ; C52.1@98.1,40.75 98.75,40.75 107,32.5 107,30.7
SIG205: Q4.G R33.2 R134.2 R135.2 TP12.1 | length 36
  TOP w0.3: TP12.1@180.938,108.3 181.585,107.265 183.1,105.75 195.85,105.75 196.4,105.2 196.4,104.35 ; 196.05,104 196.4,104.35 ; 196.75,104 196.4,104.35 ; Q4.G@196.8,101.5 Q4.G@196.78,101.5 196.4,101.5 196.4,104.35
  TOP w0.6: 196.6,99.25 197.2,98.65 ; Q4.G@196.8,101.5 197.2,101.1 197.2,98.65 ; 197.8,99.25 197.2,98.65 ; R134.2@199.1,90.5 R135.2@199.1,92.75 199.1,94.15 199,94.25 R33.2@199,95.2 199,96.25 197.2,98.05 197.2,98.65
  TOP w0.8: TP12.1@180.75,108.6 TP12.1@180.938,108.3
SIG206: Q3.G R31.2 R126.2 R127.2 TP11.1 | length 21.1
  TOP w0.3: TP11.1@173.935,108.123 174.319,107.131 178.014,103.436 179.393,101.509 Q3.G@179.4,101.5
  TOP w0.6: R31.2@173.6,95.9 173.95,96.25 R127.2@176.1,96.25 177.05,95.3 R126.2@178.4,95.3 ; R126.2@178.4,95.6 178.4,96.5 179.4,97.5 Q3.G@179.4,101.5
  TOP w0.8: TP11.1@173.75,108.6 TP11.1@173.935,108.123
  TOP w1: R126.2@178.4,95.3 R126.2@178.4,95.6
SIG223: C66.2 IC11.2 R130.2 | length 2.8
  BOTTOM w0.6: IC11.2@194.7,58.45 C66.2@196.25,58.45 R130.2@197.5,58.45
SIG228: IC13.5 R153.2 | length 3.7
  BOTTOM w0.3: 253.94,41.1 253.24,40.4 253.94,41.1 ; 253.94,41.1 253.945,41.1 ; 253.94,41.1 253.945,41.1 ; 253.945,41.1 254.5,41.3 253.945,41.1
  BOTTOM w0.8: IC13.5@254.5,41.3 IC13.5@254.75,41.3 IC13.5@254.5,41.3
SIG229: C71.2 IC13.6 R157.2 | length 3
  BOTTOM w0.4: R157.2@253.275,41.8 C71.2@253.275,43.1 253.75,43.1 254.08,42.77 254.55,42.77 IC13.6@254.75,42.57
SIG230: IC13.1 R149.1 | length 1.5
  BOTTOM w0.4: IC13.1@264.25,42.55 R149.1@265.8,42.55
SIG231: C72.2 IC14.6 R160.2 | length 3.1
  BOTTOM w0.4: R160.2@253.275,37.3 C72.2@253.275,38.6 ; C72.2@253.3,38.6 253.75,38.6 254.38,37.97 254.55,37.97 IC14.6@254.75,37.77
SIG234: IC14.5 R154.2 | length 3.5
  BOTTOM w0.3: 253.84,36.5 253.24,35.9 253.84,36.5 ; 253.84,36.5 254.5,36.5 253.84,36.5
  BOTTOM w0.8: IC14.5@254.5,36.5 IC14.5@254.75,36.5 IC14.5@254.5,36.5
SIG236: IC14.1 R150.1 | length 1.5
  BOTTOM w0.4: IC14.1@264.25,37.8 R150.1@265.8,37.8
SIG237: C73.2 IC15.6 R163.2 | length 2.7
  TOP w0.4: C73.2@253.3,39.575 253.775,39.575 254.03,39.83 254.55,39.83 IC15.6@254.75,40.03 ; C73.2@253.3,39.6 R163.2@253.3,40.7
SIG242: IC15.5 R155.2 | length 3.6
  TOP w0.3: 253.79,41.55 253.24,42.1 253.79,41.55 ; 253.79,41.55 253.955,41.55 ; 253.79,41.55 253.955,41.55 ; 253.955,41.55 254.5,41.3 253.955,41.55
  TOP w0.8: IC15.5@254.5,41.3 IC15.5@254.75,41.3 IC15.5@254.5,41.3
SIG243: IC16.1 R152.1 | length 1.3
  TOP w0.4: IC16.1@264.53,35.23 R152.1@265.8,35.23
SIG245: IC16.5 R156.2 | length 3.8
  TOP w0.3: 254.04,36.7 253.24,37.5 254.04,36.7 ; 254.04,36.7 254.053,36.7 ; 254.04,36.7 254.053,36.7 ; 254.053,36.7 254.5,36.5 254.053,36.7
  TOP w0.8: IC16.5@254.5,36.5 IC16.5@254.75,36.5 IC16.5@254.5,36.5
SIG246: C74.2 IC16.6 R166.2 | length 2.7
  TOP w0.4: C74.2@253.325,34.95 R166.2@253.325,36.1 ; C74.2@253.35,34.95 254,34.95 254.28,35.23 IC16.6@254.75,35.23
SIG247: IC15.1 R151.1 | length 1.5
  TOP w0.4: IC15.1@264.25,40.03 R151.1@265.8,40.03
SIG249: C18.1 D23.A IC5.11 L3.1 Q5.S Q6.D R28.1 TP15.1 | length 41.5
  TOP w0.3: TP15.1@192.875,137.3 194.15,137.3 195.15,136.3 v1(196.9,136.3)
  TOP w0.45: IC5.11@174.553,127.1 IC5.11@174.7,127.1 175.75,127.1 176.3,127.65 C18.1@176.3,127.925
  TOP w0.6: R28.1@166.2,138.75 173.85,138.75 ; 173.8,141.5 174.4,140.9 ; Q5.S@174.4,143.8 174.4,140.9 ; 175,141.5 174.4,140.9 ; C18.1@176.4,127.85 177.1,127.85 178.25,129 178.25,135.25 176.9,136.6 D23.A@175.95,136.6 175.95,137.75 174.95,138.75 ; 173.85,138.75 174.4,139.3 ; 173.85,138.75 174.4,138.75 ; 174.4,138.75 174.4,139.3 ; 174.4,138.75 174.95,138.75 ; 174.4,139.3 174.4,140.9 ; 174.4,139.3 174.95,138.75
  TOP w1.7: TP15.1@191.8,137.3 TP15.1@192.875,137.3
  Mid-Layer 2 w0.6: 194.25,136.3 v1(196.9,136.3)
SIGN254: D30.A R172.1 | length 1.5
  TOP w0.7: R172.1@172.15,63.25 172.15,63.9 172.25,64 D30.A@172.25,64.7
SIGN255: D32.A R173.1 | length 1.6
  TOP w0.7: R173.1@155.65,65.6 156.25,65.6 156.4,65.45 D32.A@157.2,65.45
SIGN256: C77.2 IC3.10 R96.2 R97.1 R177.1 | length 6.5
  TOP w0.3: R177.1@164.567,22.3 v1(165.65,22.3)
  TOP w0.7: R177.1@164.35,22.3 R177.1@164.567,22.3
  BOTTOM w0.3: 166.55,23.85 IC3.10@166.55,24.55
  BOTTOM w0.4: R97.1@164.55,21.8 164.7,21.95 165.3,21.95 v1(165.65,22.3) 165.95,22 166.35,22 R96.2@166.55,21.8 C77.2@166.55,23.15 166.55,23.85
SIGN260: C76.2 IC3.9 R170.2 | length 7
  BOTTOM w0.3: IC3.9@166.575,25.225 167.425,25.225 168.45,24.2 169.075,24.2 170.575,22.7 C76.2@170.575,22.363 ; C76.2@170.575,22.2 171.075,21.7 R170.2@171.663,21.7
  BOTTOM w0.45: C76.2@170.575,22.2 C76.2@170.575,22.363
  BOTTOM w0.58: R170.2@171.663,21.7 R170.2@171.86,21.7
SIGN262: C75.2 IC3.8 R169.2 | length 6.7
  BOTTOM w0.3: IC3.8@166.55,25.875 167.675,25.875 168.65,24.9 169.675,24.9 C75.2@170.075,24.5 170.075,24.075 171.05,23.1 R169.2@171.663,23.1
  BOTTOM w0.58: R169.2@171.663,23.1 R169.2@171.86,23.1
SIGN266: FB1.2 Q2.G TP3.1 | length 20.2
  TOP w0.3: TP3.1@176.65,61.5 180.85,65.7 180.85,69.35 180.25,69.95 FB1.2@179.35,69.95
  TOP w1: Q2.G@173.68,76.2 178.85,71.03 178.85,70.05 FB1.2@178.95,69.95
  TOP w1.3: FB1.2@178.95,69.95 FB1.2@179.35,69.95
SIGN267: FB2.2 Q1.G TP4.1 | length 18.4
  TOP w0.3: 142.1,78.65 142.5,79.05 ; Q1.G@142.5,76.2 142.5,79.05 ; 142.9,78.65 142.5,79.05 ; TP4.1@144.8,83.9 144,83.9 142.5,82.4 142.5,79.05
  TOP w1: FB2.2@141.5,69.9 141.5,71.759 142.25,72.509 142.25,73.4 ; 141.75,73.9 142.25,73.4 ; Q1.G@142.5,76.2 142.25,75.95 142.25,73.4 ; 142.75,73.9 142.25,73.4
SIGN269: D23.C D42.A D43.C IC5.12 | length 12.5
  TOP w0.6: D42.A@172.4,134.6 D23.C@175,134.6 ; D43.C@172.4,136.7 D42.A@172.4,134.4 172.4,133.5 173.25,132.65 173.25,128.7 173.58,128.37 IC5.12@174.7,128.37
SIGN270: C55.2 C86.2 C87.2 IC5.7 R114.1 R123.2 | length 1.7
  TOP w0.6: C87.2@169.225,120.55 R114.1@170.95,120.55
SIGN271: R178.1 R179.2 | length 2.3
  BOTTOM w1.5: R179.2@188.15,38.3 R178.1@188.15,40.6
SIGN275: D48.A D50.A | length 3
  TOP w0.3: D50.A@105.3,99.138 106.912,99.138 107.3,98.75 D48.A@107.3,98.429
  TOP w0.4: D48.A@107.3,98.05 D48.A@107.3,98.429
  TOP w0.7: D50.A@105.2,99.138 D50.A@105.3,99.138
SIGN284: IC13.3 R194.1 | length 1.5
  BOTTOM w0.4: IC13.3@264.25,40.03 R194.1@265.8,40.03
SIGN287: IC14.3 R195.1 | length 1.5
  BOTTOM w0.4: IC14.3@264.25,35.23 R195.1@265.8,35.23
SIGN289: IC16.3 R197.1 | length 1.5
  TOP w0.4: IC16.3@264.25,37.8 R197.1@265.8,37.8
SIGN291: IC15.3 R196.1 | length 1.5
  TOP w0.4: IC15.3@264.25,42.6 R196.1@265.8,42.6
SIGN304: IC21.2 R153.1 R186.1 | length 2.9
  BOTTOM w0.4: IC21.2@249.05,40.8 249.675,40.8 249.875,40.6 R186.1@250.5,40.6 251.6,40.6 R153.1@251.8,40.4
SIGN305: IC22.2 R154.1 R188.1 | length 3.1
  BOTTOM w0.4: IC22.2@249.05,36.5 249.65,36.5 250.05,36.1 250.5,36.1 250.5,35.9 R154.1@251.8,35.9
SIGN314: IC23.2 R155.1 R190.1 | length 3.8
  TOP w0.4: IC23.2@248.95,40.6 249.85,40.6 250.25,41 R190.1@250.5,41 250.5,41.65 250.85,42 R155.1@251.8,42
SIGN315: IC24.2 R156.1 R192.1 | length 3.2
  TOP w0.4: IC24.2@248.95,36.4 249.6,36.4 250.4,37.2 R192.1@250.5,37.2 ; R192.1@250.55,37.3 251.6,37.3 R156.1@251.8,37.5
SIGN318: D24.C D40.A D41.C IC4.12 | length 16.2
  TOP w0.6: D24.C@172.6,90.8 173.9,89.5 174.9,89.5 177.2,91.8 180.25,91.8 D41.C@181.5,93.05 183.05,93.05 D40.A@183.6,92.5 ; D40.A@183.65,92.45 184.83,91.27 IC4.12@184.83,89.95
SIGN322: D22.C D46.A D47.C IC5.6 | length 35.7
  TOP w0.6: IC5.6@169.3,124.56 170.94,124.56 173.1,122.4 v1(176.2,122.4)
  BOTTOM w0.6: v1(176.2,122.4) 176.2,123.95 185.7,133.45 191.75,133.45 192.65,134.35 D22.C@192.65,135.1 D46.A@190.1,135.1 ; D46.A@190.1,135 D47.C@190.1,137.3
SIGN325: D25.C D44.A D45.C IC4.6 | length 12.1
  TOP w0.6: IC4.6@188.64,84.55 188.64,86.59 190.85,88.8 190.85,89.85 D44.A@191.5,90.5 D45.C@191.5,92.7 ; D25.C@188.9,93.2 189.35,92.75 D45.C@191.5,92.75
SIGN336: D53.C R20.1 | length 1.6
  BOTTOM w0.6: D53.C@280.1,113 R20.1@281.7,113
SIGN337: D54.A R213.1 | length 1.6
  BOTTOM w0.6: D54.A@280.1,115.25 R213.1@281.7,115.25
SIGN338: D51.C R18.1 | length 2.2
  BOTTOM w0.6: D51.C@274.05,129.55 R18.1@275.6,131.1
SIGN339: D52.A R212.1 | length 3
  BOTTOM w0.6: D52.A@273.85,131.8 274.85,132.8 ; R212.1@275.45,133.4 274.85,132.8 ; R212.1@275.6,132.8 274.85,132.8
SIGN341: D57.C R24.1 | length 1.7
  BOTTOM w0.6: D57.C@280.4,70.3 R24.1@282.1,70.3
SIGN342: D58.A R215.1 | length 1.6
  BOTTOM w0.6: D58.A@280.4,72.45 R215.1@282,72.45
SIGN343: Q7.4 Q8.4 R22.2 R23.2 R214.2 TP22.1 | length 21.3
  TOP w0.6: TP22.1@276.45,96.45 v1(277.75,96.45) ; Q7.4@276.75,107.05 v1(276.75,108.05)
  Mid-Layer 3 w0.6: v1(276.75,108.05) v1(276.75,102.25) 276.75,101.3 278,100.05 278,96.7 v1(277.75,96.45)
  BOTTOM w0.5: R22.2@278.2,91.3 278.8,91.9 R23.2@278.8,93.1
  BOTTOM w0.6: v1(276.75,102.25) Q8.4@276.75,103.245 ; v1(277.75,96.45) 278.8,95.4 R214.2@278.8,95.3 R23.2@278.8,93.1
SIGN344: D55.C R23.1 | length 2.2
  BOTTOM w0.6: D55.C@274.05,91.55 R23.1@275.6,93.1
SIGN345: D56.A R214.1 | length 2.8
  BOTTOM w0.6: D56.A@273.85,93.8 274.85,94.8 ; R214.1@275.4,94.8 274.85,94.8 ; R214.1@275.45,95.4 274.85,94.8
SIGN355: C103.2 D19.C Q3.D Q5.D T4.1 | length 198.1
  TOP w3.5: 209.5,91.7 209.5,91.6 209.5,87.5 209.528,87.472 cw(c206.7,84.643) 210.7,84.643 210.7,78.825 ccw(c216.7,78.825) 212.457,74.583 218.64,68.4 ccw(c223.589,73.35) 223.589,66.35 235.117,66.35 ; T4.1@245.11,61 244.195,61 241.481,63.714 ; 235.117,66.35 cw(c235.117,57.35) 241.481,63.714 ; 235.117,66.35 cw(c235.117,57.35) 241.481,63.714
  BOTTOM w1: 175.05,112.8 175.8,112.05 ; 175.1,111.35 175.8,112.05 ; D19.C@204.95,112.5 202.45,115 193.05,115 190.1,112.05 175.8,112.05
  BOTTOM w3: Q5.D@168.95,143.8 168.95,137.25 169.47,136.73 169.47,119.58 173.625,115.425 173.95,115.1 Q3.D@173.95,101.5
  BOTTOM w3.5: 204.95,92.05 206.8,90.2 207.3,89.7 207.8,89.2 208.3,88.7 208.8,88.2 209.528,87.472 cw(c206.7,84.643) 210.7,84.643 210.7,78.825 ccw(c216.7,78.825) 212.457,74.583 218.64,68.4 ccw(c223.589,73.35) 223.589,66.35 235.122,66.35 ; 235.122,66.35 cw(c235.122,57.35) 241.486,63.714 244.2,61 T4.1@245.11,61
  other v1: 209.2,88.6 210.2,88.6 211.2,88.6 208.2,89.6 209.2,89.6 210.2,89.6 211.2,89.6 208.2,90.6 209.2,90.6 210.2,90.6 211.2,90.6 208.2,91.6 209.2,91.6 210.2,91.6 211.2,91.6 208.2,92.6 209.2,92.6 210.2,92.6 211.2,92.6 208.2,93.6 209.2,93.6 210.2,93.6 211.2,93.6 209.2,94.6 210.2,94.6
SIGN356: D14.A R9.2 T4.5 | length 3.8
  BOTTOM w0.6: T4.5@262.89,48.3 D14.A@265.35,48.3 R9.2@265.35,49.65
SIGN360: L5.1 T5.7 T5.8 T5.9 T5.13 TP18.1 | length 4.8
  BOTTOM w2.8: L5.1@282.25,53.4 L5.1@282.25,55.8 L5.1@282.25,58.2
SIGN364: C64.2 IC20.4 L12.1 R138.1 | length 72.3
  TOP w5: 96.1,73.7 98.54,73.7 103.415,68.825 108.41,68.825 109.985,70.4 112.275,70.4 ; 113.35,63.55 C64.2@113.35,61.6 122.75,52.2 L12.1@124.9,52.2
  BOTTOM w5: 96.1,73.7 98.54,73.7 103.415,68.825 108.41,68.825 109.985,70.4 112.275,70.4 ; 113.35,63.55 C64.2@113.35,61.6 122.75,52.2 124.75,52.2
SIGN366: HS1.1 R220.2 | length 5.3
  TOP w0.5: HS1.1@149.55,91.1 149.6,88.25 R220.2@149.6,86.127
  TOP w0.72: R220.2@149.6,85.84 R220.2@149.6,85.9 R220.2@149.6,86.127
SIGN369: HS2.1 R221.2 | length 5.3
  TOP w0.5: HS2.1@203,81.5 R221.2@203,86.517
  TOP w0.7: R221.2@203,86.517 R221.2@203,86.8
SIGN371: HS3.1 R222.2 | length 5.3
  TOP w0.5: HS3.1@136.25,70 136.3,67.15 R222.2@136.3,65.017
  TOP w0.6: R222.2@136.3,64.75 R222.2@136.3,64.8 R222.2@136.3,65.017
SIGN373: HS4.1 R223.2 | length 5.8
  TOP w0.5: HS4.1@202.45,106.65 204.6,104.5 R223.2@204.6,102.017
  TOP w0.6: R223.2@204.6,101.75 R223.2@204.6,102.017
VCC3R3_1: C95.2 C96.2 C97.2 C98.2 IC21.5 IC22.5 IC23.5 IC24.5 R117.2 R157.1 R160.1 R163.1 R166.1 R186.2 R188.2 R190.2 R192.2 | length 109.9
  TOP w0.4: C98.2@245.6,35.825 246.175,35.825 246.25,35.75 IC24.5@247.05,35.75 ; C97.2@245.6,39.95 IC23.5@247.1,39.95
  TOP w0.45: v1(244.7,36.25) 245.125,35.825 C98.2@245.6,35.825 ; v1(244.7,40.3) 245.075,39.925 C97.2@245.6,39.925
  TOP w0.5: v1(250.6,38.25) 250.5,38.35 R190.2@250.5,39.6 251.4,39.6 251.8,40 R163.1@251.8,40.7
  TOP w0.6: v1(195.5,55.45) v1(196.35,55.45) ; v1(250.5,34.95) R192.2@250.5,35.8 251.35,35.8 251.65,36.1 R166.1@251.8,36.1
  Mid-Layer 2 w0.8: v1(195.5,55.45) v1(196.35,55.45) 211.3,55.45 216.5,50.25 216.5,48.45 218.8,46.15 218.8,43.75 225.2,37.35 v1(241.45,37.35)
  Mid-Layer 3 w0.5: v1(244.7,36.25) 246.75,36.25 247.85,37.35 ; 248.65,40.3 250.1,40.3 ; v1(250.5,34.95) 250.6,35.05 v1(250.6,38.25) 250.6,39.8 ; v1(250.6,43) 250.6,40.8 ; 250.1,40.3 250.6,40.8 ; 250.1,40.3 250.6,39.8 ; 250.6,39.8 250.6,40.8
  Mid-Layer 3 w0.8: v1(241.45,37.35) 241.45,38.55 243.2,40.3 v1(244.7,40.3) 247.05,40.3 ; 247.85,37.35 247.85,39.5 ; 250.1,40.3 248.65,40.3 ; 247.05,40.3 247.85,39.5 ; 247.05,40.3 247.85,40.3 248.65,40.3 ; 247.85,39.5 248.65,40.3
  BOTTOM w0.45: v1(244.7,36.25) 245.225,36.775 C96.2@245.7,36.775 246.025,36.775 246.4,37.15 IC22.5@247.15,37.15 ; v1(244.7,40.3) 244.7,40.7 245.025,41.025 C95.2@245.7,41.025 245.975,41.025 246.4,41.45 IC21.5@247.15,41.45
  BOTTOM w0.5: v1(250.6,38.25) 250.5,38.15 R188.2@250.5,37.35 R160.1@251.8,37.35 ; v1(250.6,43) 250.5,42.9 R186.2@250.5,42 250.85,42 251.05,41.8 R157.1@251.8,41.8
  BOTTOM w0.8: v1(195.5,55.45) v1(196.35,55.45) 196.9,55.45 R117.2@197.3,55.85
